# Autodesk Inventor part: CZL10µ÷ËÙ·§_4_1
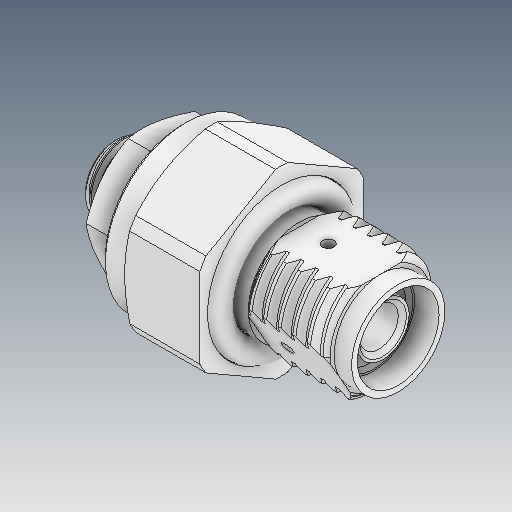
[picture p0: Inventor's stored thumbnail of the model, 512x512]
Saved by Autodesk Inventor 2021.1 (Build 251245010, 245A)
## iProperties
Created: 2021-05
Part Number: CZL10µ÷ËÙ·§_4_1
Material: Ogólny
Document SubType Name: Modeling
Designer: user
Density: 1 g/cm^3
Appearance: Domyślna
Author: user
Revision Number: ÈÎºÎ
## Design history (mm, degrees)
feature "ÊäÈë1"
feature "ÊäÈë2"
feature "ÊäÈë3"
node "Bryła1"
node "Bryła2"
node "Bryła3"
